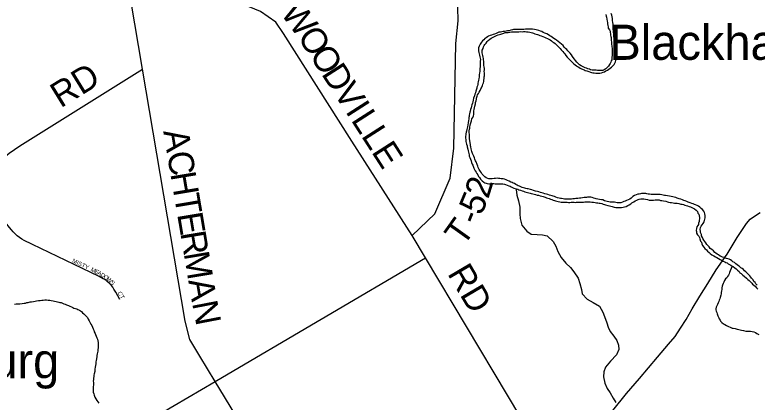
# Model space of a CAD drawing. Extents: x 0 to 1064, y 0 to 440.
# Drawn here: x 324.39 to 351.06, y 97.69 to 111.62 of the extents above; entities that cross this region are included whole.
import ezdxf

# ---------------------------------------------------------------- set-up
doc = ezdxf.new("R2010")
doc.units = 0
for name, color, linetype in [('GM_X_County_Road', 7, 'Continuous'), ('GM_X_County_Road_Text', 7, 'Continuous'), ('GM_X_Minor_River', 7, 'Continuous'), ('GM_X_State_Route', 7, 'Continuous'), ('GM_X_Township_Road', 7, 'Continuous'), ('GM_X_Township_Road_Text', 7, 'Continuous'), ('GM_X_Township_Subdivision', 7, 'Continuous'), ('GM_X_Township_Subdivision_Text', 7, 'Continuous'), ('GM_X_Unincorporated_Text', 7, 'Continuous')]:
    doc.layers.add(name, color=color, linetype=linetype)

msp = doc.modelspace()

# ---------------------------------------------------------------- linework, layer by layer
at = {"layer": 'GM_X_County_Road'}
msp.add_lwpolyline([(343.796, 94.957), (343.565, 95.473), (339.148, 102.88), (338.67, 103.68), (336.501, 107.081), (334.047, 110.954), (333.774, 111.359), (333.214, 111.744), (328.278, 113.796), (325.052, 115.154), (324.245, 115.494), (324.036, 115.585), (324.025, 115.59)], dxfattribs=at)
at = {"layer": 'GM_X_Minor_River'}
for points in [[(345.621, 111.63), (345.638, 111.575), (345.649, 111.532), (345.666, 111.465), (345.676, 111.398), (345.687, 111.349), (345.692, 111.294), (345.697, 111.239), (345.708, 111.196), (345.713, 111.142), (345.76, 111.086), (345.777, 111.031), (345.782, 110.988), (345.793, 110.939), (345.798, 110.896), (345.809, 110.847), (345.814, 110.805), (345.818, 110.738), (345.823, 110.695), (345.828, 110.652), (345.833, 110.604), (345.832, 110.555), (345.837, 110.512), (345.842, 110.47), (345.853, 110.427), (345.857, 110.36), (345.856, 110.305), (345.854, 110.226), (345.852, 110.159), (345.845, 110.099), (345.838, 110.05), (345.837, 110.008), (345.823, 109.965), (345.804, 109.923), (345.785, 109.875), (345.753, 109.833), (345.727, 109.779), (345.678, 109.732), (345.622, 109.685), (345.572, 109.649), (345.523, 109.62), (345.48, 109.615), (345.437, 109.616), (345.37, 109.618), (345.328, 109.619), (345.285, 109.626), (345.231, 109.627), (345.176, 109.628), (345.133, 109.636), (345.079, 109.649), (345.037, 109.662), (344.982, 109.682), (344.934, 109.701), (344.88, 109.721), (344.838, 109.74), (344.789, 109.759), (344.735, 109.791), (344.675, 109.829), (344.616, 109.879), (344.586, 109.922), (344.533, 109.978), (344.498, 110.028), (344.457, 110.084), (344.427, 110.127), (344.392, 110.182), (344.345, 110.238), (344.309, 110.282), (344.256, 110.325), (344.22, 110.369), (344.172, 110.413), (344.125, 110.462), (344.09, 110.518), (344.03, 110.562), (343.971, 110.618), (343.911, 110.668), (343.857, 110.706), (343.815, 110.731), (343.761, 110.769), (343.713, 110.801), (343.66, 110.845), (343.618, 110.87), (343.57, 110.901), (343.51, 110.933), (343.437, 110.965), (343.377, 110.985), (343.323, 111.017), (343.281, 111.036), (343.22, 111.056), (343.166, 111.069), (343.118, 111.083), (343.069, 111.09), (342.996, 111.104), (342.929, 111.105), (342.85, 111.107), (342.789, 111.103)], [(343.126, 110.93), (343.168, 110.911), (343.21, 110.898), (343.259, 110.878), (343.301, 110.865), (343.361, 110.84), (343.421, 110.814), (343.476, 110.794), (343.53, 110.769), (343.578, 110.749), (343.626, 110.724), (343.674, 110.686), (343.716, 110.655), (343.764, 110.629), (343.812, 110.586), (343.865, 110.536), (343.907, 110.492), (343.948, 110.448), (343.99, 110.405), (344.025, 110.361), (344.085, 110.305), (344.12, 110.256), (344.149, 110.213), (344.19, 110.157), (344.238, 110.101), (344.273, 110.058), (344.333, 110.007), (344.38, 109.958), (344.428, 109.908), (344.481, 109.858), (344.523, 109.82), (344.571, 109.783), (344.613, 109.758), (344.655, 109.738), (344.703, 109.707), (344.751, 109.681), (344.793, 109.662), (344.847, 109.642), (344.89, 109.623), (344.944, 109.604), (345.01, 109.584), (345.071, 109.564), (345.113, 109.551), (345.155, 109.538), (345.21, 109.53), (345.265, 109.529), (345.325, 109.521), (345.368, 109.52), (345.411, 109.525), (345.472, 109.536), (345.533, 109.559), (345.576, 109.576), (345.632, 109.605), (345.687, 109.634), (345.731, 109.67), (345.786, 109.705), (345.83, 109.74), (345.886, 109.794), (345.93, 109.835), (345.955, 109.883), (345.975, 109.931), (345.988, 109.974), (346.001, 110.022), (346.015, 110.07), (346.016, 110.125), (346.017, 110.18), (346.018, 110.222), (346.014, 110.277), (346.01, 110.356), (346.005, 110.399), (346, 110.448), (345.989, 110.503), (345.978, 110.57), (345.961, 110.613), (345.951, 110.686), (345.94, 110.729), (345.929, 110.79), (345.918, 110.833), (345.919, 110.875), (345.909, 110.948), (345.904, 110.991), (345.899, 111.052), (345.894, 111.095), (345.889, 111.143), (345.891, 111.21), (345.886, 111.271), (345.876, 111.357), (345.871, 111.411), (345.861, 111.491), (345.851, 111.552), (345.84, 111.607), (345.823, 111.674)], [(342.789, 111.103), (342.741, 111.104), (342.68, 111.099), (342.637, 111.094), (342.588, 111.089), (342.533, 111.091), (342.479, 111.092), (342.418, 111.093), (342.363, 111.089), (342.314, 111.09), (342.271, 111.079), (342.21, 111.068), (342.155, 111.051), (342.094, 111.046), (342.045, 111.035), (341.99, 111.025), (341.941, 111.02), (341.892, 111.015), (341.837, 111.004), (341.788, 110.993), (341.733, 110.97), (341.684, 110.953), (341.622, 110.93), (341.573, 110.919), (341.518, 110.89), (341.475, 110.873), (341.413, 110.85), (341.37, 110.827), (341.327, 110.797), (341.284, 110.768), (341.24, 110.727), (341.19, 110.685), (341.159, 110.643), (341.114, 110.571), (341.076, 110.493), (341.05, 110.439), (341.049, 110.378), (341.053, 110.33), (341.058, 110.263), (341.086, 110.165), (341.103, 110.11), (341.114, 110.067), (341.119, 110.018), (341.117, 109.957), (341.116, 109.897), (341.114, 109.842), (341.107, 109.799), (341.106, 109.751), (341.105, 109.696), (341.097, 109.642), (341.096, 109.587), (341.088, 109.532), (341.075, 109.46), (341.073, 109.387), (341.065, 109.32), (341.052, 109.272), (341.044, 109.211), (341.031, 109.163), (341.023, 109.114), (341.01, 109.072), (340.997, 109.024), (340.99, 108.981), (340.97, 108.915), (340.956, 108.873), (340.943, 108.818), (340.924, 108.77), (340.904, 108.704), (340.877, 108.625), (340.863, 108.553), (340.844, 108.493), (340.83, 108.444), (340.817, 108.39), (340.797, 108.336), (340.784, 108.281), (340.77, 108.221), (340.756, 108.16), (340.743, 108.118), (340.729, 108.064), (340.722, 108.015), (340.715, 107.967), (340.708, 107.924), (340.7, 107.87), (340.693, 107.821), (340.679, 107.743), (340.665, 107.664), (340.651, 107.597), (340.65, 107.543), (340.636, 107.494), (340.623, 107.44), (340.609, 107.398), (340.602, 107.343), (340.595, 107.301), (340.588, 107.252), (340.586, 107.198), (340.591, 107.131), (340.595, 107.07), (340.606, 107.021), (340.623, 106.966), (340.64, 106.91), (340.645, 106.868), (340.667, 106.788)], [(340.742, 107.096), (340.732, 107.164), (340.727, 107.225), (340.723, 107.292), (340.724, 107.334), (340.719, 107.383), (340.72, 107.45), (340.728, 107.504), (340.735, 107.547), (340.742, 107.595), (340.756, 107.643), (340.763, 107.698), (340.776, 107.74), (340.802, 107.813), (340.816, 107.879), (340.842, 107.933), (340.868, 107.993), (340.887, 108.035), (340.888, 108.078), (340.878, 108.169), (340.891, 108.212), (340.911, 108.278), (340.925, 108.332), (340.939, 108.417), (340.946, 108.466), (340.966, 108.532), (340.974, 108.587), (340.981, 108.629), (341.007, 108.701), (341.02, 108.744), (341.052, 108.791), (341.078, 108.846), (341.109, 108.9), (341.141, 108.954), (341.16, 108.996), (341.199, 109.08), (341.212, 109.122), (341.226, 109.176), (341.239, 109.225), (341.246, 109.267), (341.26, 109.334), (341.261, 109.388), (341.263, 109.431), (341.264, 109.486), (341.265, 109.54), (341.26, 109.583), (341.262, 109.638), (341.263, 109.686), (341.258, 109.747), (341.247, 109.802), (341.243, 109.863), (341.238, 109.906), (341.239, 109.954), (341.234, 110.009), (341.229, 110.052), (341.218, 110.101), (341.207, 110.156), (341.191, 110.211), (341.186, 110.254), (341.18, 110.296), (341.188, 110.351), (341.214, 110.411), (341.234, 110.471), (341.259, 110.513), (341.278, 110.555), (341.322, 110.603), (341.366, 110.657), (341.404, 110.704), (341.46, 110.752), (341.509, 110.781), (341.558, 110.804), (341.602, 110.833), (341.651, 110.856), (341.7, 110.88), (341.756, 110.903), (341.805, 110.92), (341.848, 110.931), (341.89, 110.942), (341.958, 110.965), (342.013, 110.982), (342.062, 110.986), (342.123, 110.991), (342.172, 110.996), (342.239, 111.006), (342.282, 111.012), (342.337, 111.01), (342.391, 111.009), (342.446, 111.014), (342.501, 111.012), (342.568, 111.017), (342.623, 111.015), (342.672, 111.02), (342.733, 111.019), (342.781, 111.012), (342.842, 111.01), (342.896, 110.997), (342.945, 110.983), (342.987, 110.97), (343.029, 110.957), (343.078, 110.938), (343.126, 110.93)], [(345.335, 104.991), (345.28, 105.005), (345.238, 105.012), (345.196, 105.025), (345.141, 105.051), (345.087, 105.058), (345.026, 105.06), (344.971, 105.061), (344.929, 105.056), (344.843, 105.046), (344.794, 105.041), (344.733, 105.03), (344.678, 105.026), (344.617, 105.015), (344.544, 105.011), (344.495, 105.006), (344.446, 105.001), (344.391, 104.996), (344.336, 104.991), (344.294, 104.986), (344.245, 104.987), (344.196, 104.995), (344.142, 104.996), (344.093, 105.003), (344.039, 105.017), (343.996, 105.018), (343.948, 105.031), (343.893, 105.044), (343.833, 105.064), (343.785, 105.084), (343.736, 105.097), (343.694, 105.11), (343.652, 105.123), (343.597, 105.137), (343.537, 105.156), (343.495, 105.17), (343.434, 105.183), (343.38, 105.203), (343.325, 105.216), (343.283, 105.235), (343.223, 105.255), (343.174, 105.269), (343.102, 105.282), (343.029, 105.308), (342.969, 105.328), (342.914, 105.342), (342.842, 105.362), (342.799, 105.369), (342.757, 105.376), (342.715, 105.389), (342.666, 105.402), (342.618, 105.416), (342.57, 105.435), (342.528, 105.454), (342.479, 105.468), (342.437, 105.499), (342.395, 105.524), (342.341, 105.55), (342.299, 105.569), (342.257, 105.589), (342.215, 105.602), (342.155, 105.64), (342.095, 105.665), (342.046, 105.685), (341.986, 105.705), (341.932, 105.718), (341.865, 105.726), (341.822, 105.739), (341.774, 105.74), (341.719, 105.741), (341.658, 105.737), (341.609, 105.732), (341.548, 105.727), (341.481, 105.723), (341.426, 105.724), (341.384, 105.737), (341.33, 105.757), (341.276, 105.795), (341.223, 105.851), (341.187, 105.894), (341.158, 105.937), (341.122, 105.981), (341.075, 106.055), (341.041, 106.135), (341.03, 106.178), (341.001, 106.239), (340.967, 106.331), (340.943, 106.374), (340.92, 106.436), (340.903, 106.479), (340.88, 106.54), (340.863, 106.583), (340.834, 106.638), (340.811, 106.706), (340.8, 106.749), (340.79, 106.803), (340.779, 106.871), (340.768, 106.913), (340.763, 106.956), (340.752, 107.017), (340.742, 107.096)], [(340.667, 106.788), (340.684, 106.727), (340.689, 106.684), (340.706, 106.629), (340.711, 106.586), (340.722, 106.544), (340.739, 106.489), (340.768, 106.427), (340.791, 106.366), (340.802, 106.311), (340.825, 106.255), (340.842, 106.212), (340.871, 106.145), (340.882, 106.102), (340.911, 106.059), (340.934, 106.01), (340.964, 105.966), (340.987, 105.917), (341.022, 105.862), (341.057, 105.812), (341.087, 105.769), (341.128, 105.707), (341.181, 105.651), (341.241, 105.601), (341.283, 105.576), (341.325, 105.562), (341.367, 105.555), (341.422, 105.548), (341.501, 105.546), (341.544, 105.551), (341.599, 105.55), (341.653, 105.542), (341.702, 105.541), (341.763, 105.54), (341.805, 105.545), (341.86, 105.543), (341.927, 105.542), (341.982, 105.534), (342.024, 105.521), (342.084, 105.495), (342.145, 105.47), (342.187, 105.456), (342.229, 105.431), (342.271, 105.412), (342.325, 105.392), (342.368, 105.379), (342.416, 105.366), (342.464, 105.353), (342.506, 105.333), (342.555, 105.32), (342.621, 105.294), (342.663, 105.281), (342.712, 105.261), (342.766, 105.248), (342.808, 105.235), (342.857, 105.221), (342.905, 105.208), (342.947, 105.195), (343.008, 105.181), (343.056, 105.168), (343.105, 105.155), (343.159, 105.141), (343.208, 105.134), (343.268, 105.114), (343.322, 105.101), (343.377, 105.087), (343.443, 105.061), (343.491, 105.042), (343.54, 105.029), (343.588, 105.015), (343.636, 104.996), (343.691, 104.976), (343.733, 104.957), (343.781, 104.944), (343.824, 104.937), (343.872, 104.917), (343.914, 104.904), (343.975, 104.897), (344.017, 104.889), (344.078, 104.882), (344.133, 104.881), (344.194, 104.879), (344.242, 104.878), (344.285, 104.877), (344.334, 104.876), (344.382, 104.881), (344.431, 104.879), (344.486, 104.878), (344.534, 104.877), (344.577, 104.882), (344.62, 104.881), (344.668, 104.88), (344.717, 104.885), (344.772, 104.883), (344.827, 104.888), (344.87, 104.893), (344.912, 104.898), (344.967, 104.897), (345.016, 104.896), (345.058, 104.895), (345.125, 104.887)], [(342.416, 105.366), (342.399, 105.338), (342.432, 105.13), (342.483, 104.928), (342.534, 104.702), (342.541, 104.465), (342.55, 104.294), (342.613, 104.062), (342.786, 103.839), (342.948, 103.727), (343.156, 103.717), (343.357, 103.713), (343.515, 103.667), (343.738, 103.474), (343.826, 103.302), (343.908, 103.106), (344.026, 102.896), (344.193, 102.686), (344.354, 102.531), (344.48, 102.376), (344.634, 102.148), (344.698, 101.958), (344.748, 101.744), (344.782, 101.585), (344.962, 101.399), (345.167, 101.274), (345.396, 101.141), (345.521, 100.932), (345.579, 100.767), (345.66, 100.546), (345.712, 100.393), (345.782, 100.227), (345.913, 100.06), (346.026, 99.906), (346.084, 99.741), (346.099, 99.588), (346.01, 99.395), (345.792, 99.162), (345.616, 98.952), (345.552, 98.777), (345.543, 98.607), (345.593, 98.375), (345.675, 98.184), (345.788, 98.024), (345.888, 97.833), (345.989, 97.679)], [(349.584, 103.047), (349.542, 103.072), (349.501, 103.128), (349.436, 103.178), (349.376, 103.222), (349.34, 103.271), (349.299, 103.315), (349.258, 103.365), (349.222, 103.42), (349.181, 103.464), (349.152, 103.519), (349.111, 103.575), (349.099, 103.618), (349.07, 103.673), (349.059, 103.722), (349.031, 103.796), (349.026, 103.838), (349.021, 103.899), (349.029, 103.978), (349.055, 104.026), (349.086, 104.068), (349.124, 104.122), (349.156, 104.182), (349.169, 104.23), (349.189, 104.272), (349.196, 104.321), (349.198, 104.4), (349.181, 104.461), (349.176, 104.516), (349.153, 104.559), (349.106, 104.615), (349.058, 104.658), (348.999, 104.709), (348.957, 104.734), (348.909, 104.759), (348.854, 104.785), (348.812, 104.798), (348.764, 104.824), (348.722, 104.837), (348.662, 104.863), (348.589, 104.889), (348.541, 104.908), (348.481, 104.928), (348.426, 104.947), (348.378, 104.973), (348.324, 104.986), (348.263, 105.006), (348.185, 105.032), (348.137, 105.052), (348.082, 105.065), (348.034, 105.078), (347.979, 105.092), (347.913, 105.1), (347.846, 105.113), (347.773, 105.121), (347.731, 105.128), (347.682, 105.136), (347.634, 105.149), (347.585, 105.156), (347.543, 105.163), (347.488, 105.165), (347.427, 105.16), (347.384, 105.161), (347.324, 105.162), (347.251, 105.164), (347.196, 105.172), (347.153, 105.173), (347.105, 105.186), (347.063, 105.193), (347.008, 105.2), (346.959, 105.196), (346.91, 105.191), (346.868, 105.186), (346.819, 105.175), (346.776, 105.17), (346.714, 105.147), (346.653, 105.118), (346.597, 105.083), (346.535, 105.029), (346.485, 104.994), (346.43, 104.965), (346.368, 104.942), (346.319, 104.925), (346.27, 104.902), (346.221, 104.879), (346.166, 104.862), (346.098, 104.858), (346.038, 104.865), (345.989, 104.872), (345.941, 104.88), (345.886, 104.887), (345.837, 104.888), (345.783, 104.889), (345.74, 104.897), (345.674, 104.91), (345.631, 104.924), (345.577, 104.937), (345.517, 104.963), (345.474, 104.97), (345.395, 104.978), (345.335, 104.991)], [(345.125, 104.887), (345.186, 104.879), (345.241, 104.872), (345.289, 104.865), (345.344, 104.857), (345.386, 104.85), (345.429, 104.843), (345.489, 104.83), (345.531, 104.816), (345.574, 104.803), (345.616, 104.79), (345.694, 104.764), (345.755, 104.75), (345.803, 104.737), (345.852, 104.724), (345.93, 104.703), (345.991, 104.696), (346.046, 104.689), (346.106, 104.687), (346.149, 104.692), (346.192, 104.697), (346.247, 104.702), (346.302, 104.713), (346.357, 104.73), (346.419, 104.765), (346.462, 104.788), (346.524, 104.829), (346.567, 104.858), (346.635, 104.899), (346.685, 104.928), (346.74, 104.951), (346.783, 104.975), (346.826, 104.986), (346.881, 105.009), (346.942, 105.007), (346.997, 105), (347.052, 104.993), (347.124, 104.979), (347.185, 104.959), (347.252, 104.957), (347.337, 104.961), (347.398, 104.966), (347.459, 104.971), (347.501, 104.97), (347.544, 104.963), (347.592, 104.949), (347.635, 104.948), (347.701, 104.934), (347.78, 104.92), (347.84, 104.895), (347.883, 104.887), (347.943, 104.874), (347.992, 104.867), (348.041, 104.859), (348.095, 104.852), (348.138, 104.845), (348.186, 104.844), (348.253, 104.83), (348.319, 104.816), (348.368, 104.809), (348.416, 104.796), (348.471, 104.776), (348.519, 104.763), (348.561, 104.75), (348.616, 104.73), (348.664, 104.711), (348.712, 104.691), (348.76, 104.666), (348.814, 104.64), (348.874, 104.596), (348.915, 104.546), (348.938, 104.491), (348.968, 104.448), (348.985, 104.387), (348.989, 104.338), (348.988, 104.289), (348.981, 104.235), (348.98, 104.192), (348.96, 104.126), (348.953, 104.083), (348.927, 104.041), (348.902, 103.993), (348.882, 103.939), (348.868, 103.867), (348.879, 103.824), (348.89, 103.769), (348.925, 103.713), (348.966, 103.657), (348.99, 103.614), (349.001, 103.565), (349.029, 103.486), (349.059, 103.442), (349.075, 103.387), (349.104, 103.32), (349.145, 103.264), (349.181, 103.221), (349.24, 103.164), (349.282, 103.127), (349.335, 103.071), (349.377, 103.04), (349.437, 102.989)], [(349.437, 102.989), (349.509, 102.951), (349.563, 102.92), (349.617, 102.888), (349.677, 102.856), (349.737, 102.824), (349.785, 102.799), (349.845, 102.767), (349.9, 102.741), (349.942, 102.716), (349.984, 102.697), (350.026, 102.665), (350.074, 102.64), (350.122, 102.614), (350.163, 102.583), (350.206, 102.564), (350.266, 102.526), (350.307, 102.482), (350.361, 102.432), (350.414, 102.388), (350.438, 102.345), (350.486, 102.314), (350.551, 102.257), (350.593, 102.226), (350.682, 102.145), (350.73, 102.107), (350.772, 102.07), (350.807, 102.026), (350.867, 101.976), (350.902, 101.933), (350.95, 101.895), (350.998, 101.857), (351.045, 101.808), (351.093, 101.758)], [(351.066, 101.904), (351.012, 101.948), (350.989, 101.997), (350.947, 102.035), (350.918, 102.084), (350.865, 102.146), (350.836, 102.19), (350.8, 102.233), (350.759, 102.277), (350.693, 102.345), (350.652, 102.383), (350.604, 102.414), (350.574, 102.457), (350.52, 102.495), (350.479, 102.527), (350.431, 102.564), (350.389, 102.59), (350.347, 102.627), (350.293, 102.671), (350.246, 102.715), (350.192, 102.734), (350.156, 102.778), (350.108, 102.809), (350.06, 102.828), (350.006, 102.848), (349.963, 102.861), (349.921, 102.874), (349.879, 102.888), (349.818, 102.907), (349.776, 102.933), (349.734, 102.946), (349.674, 102.984), (349.632, 103.009), (349.584, 103.047)], [(350.163, 102.583), (350.092, 102.414), (350.073, 102.354), (350.053, 102.3), (350.034, 102.258), (349.996, 102.204), (349.97, 102.162), (349.927, 102.12), (349.895, 102.066), (349.869, 102.006), (349.844, 101.964), (349.824, 101.904), (349.811, 101.862), (349.797, 101.807), (349.79, 101.747), (349.782, 101.692), (349.775, 101.638), (349.767, 101.583), (349.76, 101.541), (349.734, 101.456), (349.72, 101.408), (349.701, 101.354), (349.688, 101.311), (349.662, 101.257), (349.636, 101.203), (349.61, 101.149), (349.591, 101.107), (349.578, 101.052), (349.577, 101.01), (349.588, 100.967), (349.611, 100.912), (349.628, 100.869), (349.656, 100.795), (349.685, 100.728), (349.702, 100.685), (349.732, 100.641), (349.749, 100.598), (349.791, 100.555), (349.856, 100.511), (349.904, 100.479), (349.958, 100.447), (350.031, 100.415), (350.091, 100.383), (350.163, 100.357), (350.206, 100.35), (350.278, 100.336), (350.345, 100.317), (350.411, 100.303), (350.502, 100.282), (350.575, 100.262), (350.66, 100.248), (350.781, 100.245), (350.83, 100.238), (350.89, 100.23), (350.945, 100.217), (351.005, 100.191), (351.053, 100.16), (351.125, 100.121)], [(324.379, 101.216), (324.434, 101.221), (324.501, 101.225), (324.574, 101.23), (324.654, 101.24), (324.727, 101.25), (324.776, 101.255), (324.825, 101.272), (324.868, 101.277), (324.941, 101.294), (324.99, 101.299), (325.063, 101.309), (325.125, 101.32), (325.174, 101.331), (325.247, 101.341), (325.302, 101.352), (325.363, 101.363), (325.412, 101.361), (325.473, 101.366), (325.527, 101.365), (325.588, 101.363), (325.649, 101.356), (325.697, 101.348), (325.764, 101.335), (325.813, 101.327), (325.873, 101.314), (325.922, 101.3), (325.97, 101.287), (326.012, 101.28), (326.055, 101.273), (326.109, 101.253), (326.157, 101.228), (326.199, 101.209), (326.248, 101.189), (326.314, 101.163), (326.362, 101.138), (326.422, 101.118), (326.471, 101.099), (326.513, 101.073), (326.573, 101.054), (326.615, 101.041), (326.658, 101.027), (326.712, 101.002), (326.783, 100.951), (326.825, 100.908), (326.867, 100.864), (326.914, 100.821), (326.956, 100.783), (326.997, 100.733), (327.032, 100.672), (327.067, 100.616), (327.102, 100.542), (327.125, 100.499), (327.155, 100.45), (327.183, 100.382), (327.206, 100.327), (327.224, 100.284), (327.246, 100.223), (327.275, 100.161), (327.286, 100.118), (327.316, 100.069), (327.332, 100.008), (327.356, 99.959), (327.372, 99.897), (327.383, 99.83), (327.388, 99.782), (327.386, 99.709), (327.384, 99.648), (327.377, 99.581), (327.369, 99.52), (327.354, 99.424), (327.341, 99.369), (327.334, 99.327), (327.32, 99.248), (327.312, 99.187), (327.305, 99.139), (327.297, 99.066), (327.289, 99.012), (327.282, 98.951), (327.268, 98.878), (327.26, 98.787), (327.239, 98.703), (327.232, 98.66), (327.225, 98.612), (327.217, 98.557), (327.216, 98.503), (327.209, 98.448)], [(327.209, 98.448), (327.213, 98.393), (327.212, 98.32), (327.203, 98.235), (327.202, 98.175), (327.206, 98.102), (327.211, 98.053), (327.228, 97.986), (327.239, 97.937), (327.267, 97.869), (327.296, 97.808), (327.337, 97.752), (327.373, 97.696), (327.408, 97.653)]]:
    msp.add_lwpolyline(points, dxfattribs=at)
at = {"layer": 'GM_X_State_Route'}
msp.add_lwpolyline([(345.878, 97.386), (346.372, 98.005), (346.839, 98.539), (347.489, 99.312), (347.88, 99.781), (348.114, 100.055), (348.312, 100.353), (348.509, 100.658), (348.734, 101.047), (349.009, 101.501), (349.296, 101.956), (349.597, 102.446), (349.986, 103.019), (350.344, 103.617), (350.676, 104.113), (350.814, 104.267), (351.001, 104.408), (351.169, 104.506)], dxfattribs=at)
at = {"layer": 'GM_X_Township_Road'}
for points in [[(341.681, 93.219), (341.453, 93.5), (340.897, 94.189), (340.075, 94.901), (338.98, 95.781), (338.504, 96.068), (337.916, 96.223), (337.442, 96.285), (337.168, 96.24), (336.819, 96.118), (334.146, 94.883), (333.926, 94.863), (333.793, 94.901), (333.542, 95.221), (331.589, 98.436), (331.038, 99.35), (330.682, 99.945), (330.509, 100.604), (328.977, 109.662), (328.278, 113.796), (327.503, 117.916), (327.452, 118.192), (327.388, 118.539)], [(338.67, 103.68), (339.48, 104.458), (340.029, 105.744), (340.168, 106.823), (340.238, 110.596), (340.324, 111.403), (340.313, 111.89), (340.068, 112.556), (339.958, 112.94), (339.98, 113.165), (340.272, 113.574), (340.373, 113.809), (340.373, 114.155), (340.566, 114.538)], [(321.351, 104.255), (322.905, 105.599), (324.193, 106.646), (324.575, 106.913), (328.977, 109.662)], [(331.652, 98.473), (339.148, 102.88)], [(324.747, 93.833), (327.286, 95.646), (327.538, 95.812), (327.856, 95.911), (327.997, 96), (328.239, 96.269), (328.389, 96.486), (328.647, 96.707), (331.589, 98.436), (331.648, 98.471), (331.652, 98.473)]]:
    msp.add_lwpolyline(points, dxfattribs=at)
at = {"layer": 'GM_X_Township_Subdivision'}
msp.add_lwpolyline([(328.159, 101.387), (328.024, 101.644), (327.951, 101.759), (327.91, 101.822), (327.865, 101.882), (327.82, 101.933), (327.771, 101.981), (327.724, 102.022), (327.675, 102.061), (327.623, 102.096), (327.568, 102.129), (327.423, 102.21), (324.726, 103.502), (324.64, 103.554), (324.557, 103.611), (324.478, 103.673), (324.403, 103.74), (324.333, 103.812), (324.267, 103.888), (324.205, 103.968), (322.905, 105.599)], dxfattribs=at)

# ---------------------------------------------------------------- texts
at = {"layer": 'GM_X_County_Road_Text'}
for s, height, rotation, p in [('W', 0.909, 305.8706, (333.912, 111.69)), ('O', 0.909, 302.6858, (334.522, 110.847)), ('O', 0.909, 302.6882, (334.954, 110.174)), ('D', 0.909, 302.6882, (335.386, 109.501)), ('V', 0.909, 302.6882, (335.818, 108.827)), ('I', 0.909, 302.69, (336.25, 108.154)), ('L', 0.909, 302.6868, (336.452, 107.84)), ('L', 0.909, 302.6858, (336.819, 107.268)), ('E', 0.909, 302.6858, (337.186, 106.695)), ('RD', 0.9091, 300.5418, (339.917, 102.318))]:
    msp.add_text(s, height=height, rotation=rotation, dxfattribs=at).set_placement(p)
at = {"layer": 'GM_X_Township_Road_Text'}
for s, height, rotation, p in [('RD', 0.9091, 31.6394, (326.035, 108.254)), ('A', 0.909, 279.5001, (329.722, 107.436)), ('C', 0.909, 279.4964, (329.854, 106.647)), ('H', 0.909, 279.4998, (329.977, 105.91)), ('2', 0.909, 72.707, (341.401, 104.978)), ('T', 0.909, 279.5006, (330.109, 105.121)), ('5', 0.909, 67.3945, (341.154, 104.375)), ('E', 0.909, 279.4976, (330.222, 104.451)), ('T', 0.909, 54.5659, (340.511, 103.265)), ('-', 0.909, 68.623, (341.02, 104.032)), ('R', 0.909, 279.5003, (330.334, 103.78)), ('M', 0.909, 279.4995, (330.457, 103.043)), ('A', 0.909, 279.5211, (330.62, 102.07)), ('N', 0.909, 280.9482, (330.757, 101.257))]:
    msp.add_text(s, height=height, rotation=rotation, dxfattribs=at).set_placement(p)
at = {"layer": 'GM_X_Township_Subdivision_Text'}
for s, height, rotation, p in [('MISTY', 0.1515, 335.2263, (326.435, 102.722)), ('M', 0.152, 332.4739, (327.103, 102.415)), ('E', 0.152, 332.4577, (327.244, 102.341)), ('A', 0.152, 331.3424, (327.338, 102.292)), ('D', 0.152, 328.1591, (327.453, 102.23)), ('O', 0.152, 327.1466, (327.566, 102.16)), ('W', 0.152, 320.0351, (327.674, 102.09)), ('S', 0.152, 314.5364, (327.804, 101.981)), ('CT', 0.1515, 300.9616, (328.074, 101.618))]:
    msp.add_text(s, height=height, rotation=rotation, dxfattribs=at).set_placement(p)
at = {"layer": 'GM_X_Unincorporated_Text'}
for s, p in [('Blackhawk', (345.756, 110.003)), ('Rossburg', (318.756, 98.549))]:
    msp.add_text(s, height=1.2636, rotation=0, dxfattribs=at).set_placement(p)

doc.saveas('drawing.dxf')
